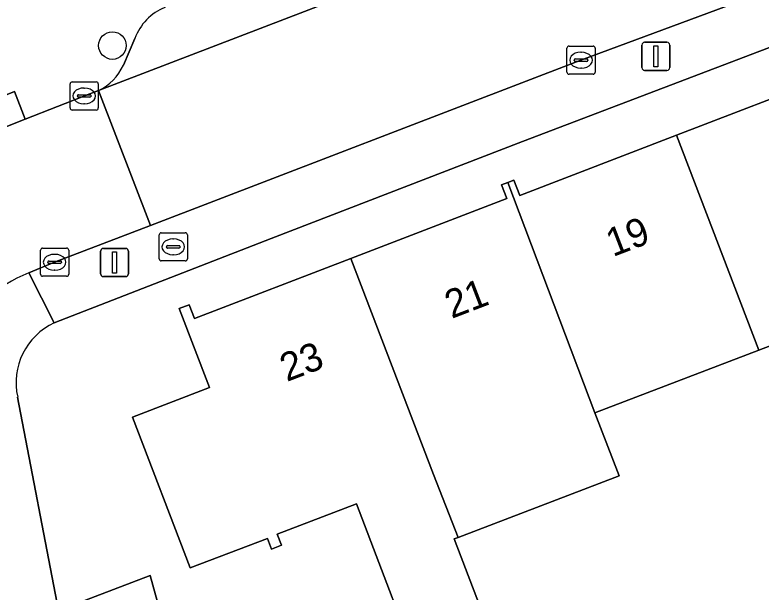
# Model space of a CAD drawing. Extents: x 159262 to 160143, y 383399 to 384319.
# Drawn here: x 159379.76 to 159406.24, y 383758.75 to 383779.23 of the extents above; entities that cross this region are included whole.
import ezdxf

# ---------------------------------------------------------------- set-up
doc = ezdxf.new("R2010")
doc.units = 0
for name, color, linetype in [('IMGEO_Boom', 7, 'Continuous'), ('IMGEO_Brandkraan', 7, 'Continuous'), ('IMGEO_Erf', 7, 'Continuous'), ('IMGEO_Kolk', 7, 'Continuous'), ('IMGEO_Lichtmast', 7, 'Continuous'), ('IMGEO_Pand', 7, 'Continuous'), ('IMGEO_Pand_nummerreeks', 7, 'Continuous'), ('IMGEO_Parkeervlak_open', 7, 'Continuous'), ('IMGEO_Rijbaan_lokaal_open', 7, 'Continuous'), ('IMGEO_Voetpad_open', 7, 'Continuous')]:
    doc.layers.add(name, color=color, linetype=linetype)

msp = doc.modelspace()

# ---------------------------------------------------------------- linework, layer by layer
at = {"layer": 'IMGEO_Boom'}
msp.add_circle((159383.218, 383778.141), 0.489, dxfattribs=at)
at = {"layer": 'IMGEO_Brandkraan'}
for p, q in [((159384.878, 383770.571), (159384.878, 383771.423)), ((159384.953, 383771.497), (159385.805, 383771.497)), ((159385.366, 383771.277), (159385.391, 383771.277)), ((159385.879, 383771.423), (159385.879, 383770.571)), ((159385.137, 383770.991), (159385.137, 383771.003)), ((159385.18, 383771.04), (159385.578, 383771.04)), ((159385.621, 383771.003), (159385.621, 383770.991)), ((159385.575, 383770.954), (159385.177, 383770.954)), ((159385.805, 383770.497), (159384.953, 383770.497)), ((159385.389, 383770.717), (159385.364, 383770.717))]:
    msp.add_line(p, q, dxfattribs=at)
for points in [[(159384.878, 383770.571), (159384.878, 383771.423)], [(159384.953, 383771.497), (159385.805, 383771.497)], [(159385.879, 383771.423), (159385.879, 383770.571)], [(159385.805, 383770.497), (159384.953, 383770.497)]]:
    msp.add_lwpolyline(points, dxfattribs=at)
for centre, radius, start, end in [((159384.955, 383771.421), 0.0765, 91.552, 178.448), ((159384.955, 383771.421), 0.0765, 91.552, 178.448), ((159385.803, 383771.421), 0.0765, 1.552, 88.448), ((159385.803, 383771.421), 0.0765, 1.552, 88.448), ((159385.177, 383771), 0.0403, 85.8775, 175.7526), ((159385.174, 383770.99), 0.0366, 178.938, 274.7102), ((159385.578, 383770.997), 0.043, 264.8664, 352.4533), ((159385.582, 383771.002), 0.0386, 1.7309, 96.639), ((159384.955, 383770.573), 0.0765, 181.552, 268.448), ((159384.955, 383770.573), 0.0765, 181.552, 268.448), ((159385.803, 383770.573), 0.0765, 271.552, 358.448), ((159385.803, 383770.573), 0.0765, 271.552, 358.448)]:
    msp.add_arc(centre, radius, start, end, dxfattribs=at)
for centre, major_axis, ratio, start_param, end_param in [((159385.365, 383770.997), (-0.387, 0.002), 0.722429, 4.712389, 7.853982), ((159385.39, 383770.997), (-0.39, 0.002), 0.717154, 1.570796, 4.712389)]:
    msp.add_ellipse(centre, major_axis=major_axis, ratio=ratio, start_param=start_param, end_param=end_param, dxfattribs=at)
at = {"layer": 'IMGEO_Erf'}
for points in [[(159454.891, 383796.495), (159397.777, 383774.733), (159388.854, 383771.293), (159381.158, 383768.297)], [(159383.927, 383764.958), (159386.663, 383766.007), (159385.588, 383768.807), (159385.945, 383768.945), (159386.133, 383768.456), (159391.678, 383770.585), (159397.219, 383772.712), (159397.031, 383773.199), (159397.25, 383773.283), (159397.468, 383773.367), (159397.676, 383772.825), (159403.232, 383774.958), (159408.79, 383777.092)], [(159411.906, 383769.536), (159406.156, 383767.336), (159400.339, 383765.112), (159401.208, 383762.87), (159395.493, 383760.684), (159395.351, 383760.63), (159397.605, 383754.719), (159397.792, 383754.791), (159401.541, 383756.23), (159402.437, 383753.896), (159417.698, 383760.02)], [(159379.857, 383765.664), (159381.308, 383758.091), (159384.559, 383759.339), (159385.65, 383755.4), (159382.115, 383753.813), (159382.7, 383750.83), (159394.45, 383755.134), (159391.879, 383761.875), (159389.07, 383760.801), (159389.22, 383760.409), (159388.866, 383760.273), (159388.72, 383760.653), (159385.981, 383759.602), (159383.927, 383764.958)]]:
    msp.add_lwpolyline(points, dxfattribs=at)
msp.add_arc((159382.118, 383766.185), 2.32, 114.4344, 192.9764, dxfattribs=at)
at = {"layer": 'IMGEO_Kolk'}
for p, q in [((159399.35, 383777.196), (159399.35, 383778.048)), ((159399.425, 383778.122), (159400.277, 383778.122)), ((159399.838, 383777.902), (159399.863, 383777.902)), ((159400.351, 383778.048), (159400.351, 383777.196)), ((159399.609, 383777.616), (159399.609, 383777.628)), ((159399.652, 383777.665), (159400.05, 383777.665)), ((159400.093, 383777.628), (159400.093, 383777.616)), ((159400.047, 383777.579), (159399.649, 383777.579)), ((159399.861, 383777.342), (159399.836, 383777.342)), ((159400.277, 383777.122), (159399.425, 383777.122)), ((159381.793, 383776.853), (159382.645, 383776.853)), ((159381.718, 383775.927), (159381.718, 383776.779)), ((159382.206, 383776.633), (159382.231, 383776.633)), ((159382.719, 383776.779), (159382.719, 383775.927)), ((159381.977, 383776.347), (159381.977, 383776.359)), ((159382.415, 383776.31), (159382.017, 383776.31)), ((159382.02, 383776.396), (159382.418, 383776.396)), ((159382.461, 383776.359), (159382.461, 383776.347)), ((159382.229, 383776.073), (159382.204, 383776.073)), ((159382.645, 383775.853), (159381.793, 383775.853)), ((159380.668, 383770.026), (159380.668, 383770.878)), ((159380.743, 383770.952), (159381.595, 383770.952)), ((159381.156, 383770.732), (159381.181, 383770.732)), ((159381.669, 383770.878), (159381.669, 383770.026)), ((159380.927, 383770.446), (159380.927, 383770.458)), ((159380.97, 383770.495), (159381.368, 383770.495)), ((159381.411, 383770.458), (159381.411, 383770.446)), ((159381.365, 383770.409), (159380.967, 383770.409)), ((159381.595, 383769.952), (159380.743, 383769.952)), ((159381.179, 383770.172), (159381.154, 383770.172))]:
    msp.add_line(p, q, dxfattribs=at)
for points in [[(159399.35, 383777.196), (159399.35, 383778.048)], [(159399.425, 383778.122), (159400.277, 383778.122)], [(159400.351, 383778.048), (159400.351, 383777.196)], [(159400.277, 383777.122), (159399.425, 383777.122)], [(159381.793, 383776.853), (159382.645, 383776.853)], [(159381.718, 383775.927), (159381.718, 383776.779)], [(159382.719, 383776.779), (159382.719, 383775.927)], [(159382.645, 383775.853), (159381.793, 383775.853)], [(159380.668, 383770.026), (159380.668, 383770.878)], [(159380.743, 383770.952), (159381.595, 383770.952)], [(159381.669, 383770.878), (159381.669, 383770.026)], [(159381.595, 383769.952), (159380.743, 383769.952)]]:
    msp.add_lwpolyline(points, dxfattribs=at)
for centre, radius, start, end in [((159399.427, 383778.046), 0.0765, 91.552, 178.448), ((159399.427, 383778.046), 0.0765, 91.552, 178.448), ((159400.275, 383778.046), 0.0765, 1.552, 88.448), ((159400.275, 383778.046), 0.0765, 1.552, 88.448), ((159399.649, 383777.625), 0.0403, 85.8775, 175.7526), ((159399.646, 383777.615), 0.0366, 178.938, 274.7102), ((159400.05, 383777.622), 0.043, 264.8664, 352.4533), ((159400.054, 383777.627), 0.0386, 1.7309, 96.639), ((159399.427, 383777.198), 0.0765, 181.552, 268.448), ((159399.427, 383777.198), 0.0765, 181.552, 268.448), ((159400.275, 383777.198), 0.0765, 271.552, 358.448), ((159400.275, 383777.198), 0.0765, 271.552, 358.448), ((159381.795, 383776.777), 0.0765, 91.552, 178.448), ((159381.795, 383776.777), 0.0765, 91.552, 178.448), ((159382.643, 383776.777), 0.0765, 1.552, 88.448), ((159382.643, 383776.777), 0.0765, 1.552, 88.448), ((159382.017, 383776.356), 0.0403, 85.8775, 175.7526), ((159382.014, 383776.346), 0.0366, 178.938, 274.7102), ((159382.418, 383776.353), 0.043, 264.8664, 352.4533), ((159382.422, 383776.358), 0.0386, 1.7309, 96.639), ((159381.795, 383775.929), 0.0765, 181.552, 268.448), ((159381.795, 383775.929), 0.0765, 181.552, 268.448), ((159382.643, 383775.929), 0.0765, 271.552, 358.448), ((159382.643, 383775.929), 0.0765, 271.552, 358.448), ((159380.745, 383770.876), 0.0765, 91.552, 178.448), ((159380.745, 383770.876), 0.0765, 91.552, 178.448), ((159381.593, 383770.876), 0.0765, 1.552, 88.448), ((159381.593, 383770.876), 0.0765, 1.552, 88.448), ((159380.967, 383770.455), 0.0403, 85.8775, 175.7526), ((159381.372, 383770.457), 0.0386, 1.7309, 96.639), ((159380.964, 383770.445), 0.0366, 178.938, 274.7102), ((159381.368, 383770.452), 0.043, 264.8664, 352.4533), ((159380.745, 383770.028), 0.0765, 181.552, 268.448), ((159380.745, 383770.028), 0.0765, 181.552, 268.448), ((159381.593, 383770.028), 0.0765, 271.552, 358.448), ((159381.593, 383770.028), 0.0765, 271.552, 358.448)]:
    msp.add_arc(centre, radius, start, end, dxfattribs=at)
for centre, major_axis, ratio, start_param, end_param in [((159399.837, 383777.622), (-0.387, 0.002), 0.722429, 4.712389, 7.853982), ((159399.862, 383777.622), (-0.39, 0.002), 0.717154, 1.570796, 4.712389), ((159382.205, 383776.353), (-0.387, 0.002), 0.722429, 4.712389, 7.853982), ((159382.23, 383776.353), (-0.39, 0.002), 0.717154, 1.570796, 4.712389), ((159381.155, 383770.452), (-0.387, 0.002), 0.722429, 4.712389, 7.853982), ((159381.18, 383770.452), (-0.39, 0.002), 0.717154, 1.570796, 4.712389)]:
    msp.add_ellipse(centre, major_axis=major_axis, ratio=ratio, start_param=start_param, end_param=end_param, dxfattribs=at)
at = {"layer": 'IMGEO_Lichtmast'}
for p, q in [((159402.007, 383777.359), (159402.007, 383778.159)), ((159402.007, 383778.159), (159402.007, 383777.359)), ((159402.107, 383778.259), (159402.897, 383778.259)), ((159402.897, 383778.259), (159402.107, 383778.259)), ((159402.997, 383778.159), (159402.997, 383777.359)), ((159402.997, 383777.359), (159402.997, 383778.159)), ((159402.897, 383777.259), (159402.107, 383777.259)), ((159402.107, 383777.259), (159402.897, 383777.259)), ((159382.8, 383770.043), (159382.8, 383770.843)), ((159382.8, 383770.843), (159382.8, 383770.043)), ((159382.9, 383770.943), (159383.69, 383770.943)), ((159383.69, 383770.943), (159382.9, 383770.943)), ((159383.79, 383770.843), (159383.79, 383770.043)), ((159383.79, 383770.043), (159383.79, 383770.843)), ((159383.69, 383769.943), (159382.9, 383769.943)), ((159382.9, 383769.943), (159383.69, 383769.943))]:
    msp.add_line(p, q, dxfattribs=at)
for points in [[(159402.427, 383778.134), (159402.577, 383778.134), (159402.577, 383777.384), (159402.427, 383777.384), (159402.427, 383778.134)], [(159383.22, 383770.818), (159383.37, 383770.818), (159383.37, 383770.068), (159383.22, 383770.068), (159383.22, 383770.818)]]:
    msp.add_lwpolyline(points, dxfattribs=at)
for centre, start, end in [((159402.107, 383778.159), 90, 180), ((159402.107, 383778.159), 90, 180), ((159402.897, 383778.159), 0, 90), ((159402.897, 383778.159), 360, 90), ((159402.107, 383777.359), 180, 270), ((159402.107, 383777.359), 180, 270), ((159402.897, 383777.359), 270, 0), ((159402.897, 383777.359), 270, 0), ((159382.9, 383770.843), 90, 180), ((159382.9, 383770.843), 90, 180), ((159383.69, 383770.843), 0, 90), ((159383.69, 383770.843), 360, 90), ((159382.9, 383770.043), 180, 270), ((159382.9, 383770.043), 180, 270), ((159383.69, 383770.043), 270, 0), ((159383.69, 383770.043), 270, 0)]:
    msp.add_arc(centre, 0.1, start, end, dxfattribs=at)
at = {"layer": 'IMGEO_Pand'}
for points in [[(159406.156, 383767.336), (159411.906, 383769.536), (159408.815, 383777.651), (159408.606, 383777.571), (159408.79, 383777.092), (159403.232, 383774.958)], [(159406.156, 383767.336), (159403.232, 383774.958), (159397.676, 383772.825), (159397.468, 383773.367), (159397.25, 383773.283), (159400.339, 383765.112)], [(159391.678, 383770.585), (159394.619, 383762.923), (159395.493, 383760.684), (159401.208, 383762.87), (159400.339, 383765.112), (159397.25, 383773.283), (159397.031, 383773.199), (159397.219, 383772.712)], [(159391.678, 383770.585), (159386.133, 383768.456), (159385.945, 383768.945), (159385.588, 383768.807), (159386.663, 383766.007), (159383.927, 383764.958), (159385.981, 383759.602), (159388.72, 383760.653), (159388.866, 383760.273), (159389.22, 383760.409), (159389.07, 383760.801), (159391.879, 383761.875), (159394.45, 383755.134), (159382.7, 383750.83), (159382.871, 383750), (159383.52, 383746.85), (159388.206, 383748.595), (159391.978, 383750), (159398.686, 383752.499), (159397.792, 383754.791), (159397.605, 383754.719), (159395.351, 383760.63), (159395.493, 383760.684), (159394.619, 383762.923)], [(159381.308, 383758.091), (159382.115, 383753.813), (159385.65, 383755.4), (159384.559, 383759.339)]]:
    msp.add_lwpolyline(points, close=True, dxfattribs=at)
at = {"layer": 'IMGEO_Parkeervlak_open'}
for points in [[(159382.731, 383776.545), (159398.361, 383782.558), (159413.843, 383788.378), (159430.813, 383794.888), (159451.704, 383802.889)], [(159384.015, 383778.392), (159383.608, 383777.443)]]:
    msp.add_lwpolyline(points, dxfattribs=at)
for centre, radius, start, end in [((159385.789, 383777.739), 1.89, 111.7958, 159.7854), ((159381.91, 383778.224), 1.869, 296.053, 335.3027)]:
    msp.add_arc(centre, radius, start, end, dxfattribs=at)
at = {"layer": 'IMGEO_Rijbaan_lokaal_open'}
msp.add_lwpolyline([(159420.987, 383785.667), (159432.691, 383790.083), (159442.971, 383794.05), (159451.565, 383797.259), (159454.155, 383798.309), (159456.91, 383799.271), (159455.084, 383804.175), (159451.704, 383802.889), (159430.813, 383794.888), (159413.843, 383788.378), (159398.361, 383782.558), (159382.731, 383776.545), (159384.569, 383771.758), (159399.847, 383777.623), (159409.934, 383781.376)], close=True, dxfattribs=at)
msp.add_lwpolyline([(159380.25, 383770.078), (159381.169, 383770.453), (159384.569, 383771.758), (159382.731, 383776.545), (159382.42, 383776.425), (159380.129, 383775.526), (159378.116, 383774.737), (159375.723, 383773.799)], dxfattribs=at)
msp.add_arc((159382.299, 383765.115), 5.369, 112.4347, 188.5158, dxfattribs=at)
at = {"layer": 'IMGEO_Voetpad_open'}
for points in [[(159458.547, 383794.996), (159457.253, 383798.289), (159454.498, 383797.327), (159454.155, 383798.309), (159451.565, 383797.259), (159442.971, 383794.05), (159432.691, 383790.083), (159420.987, 383785.667), (159409.934, 383781.376), (159399.847, 383777.623), (159384.569, 383771.758), (159381.169, 383770.453), (159380.25, 383770.078), (159381.158, 383768.297), (159388.854, 383771.293), (159397.777, 383774.733), (159454.891, 383796.495)], [(159383.608, 383777.443), (159384.015, 383778.392)], [(159375.341, 383774.766), (159377.913, 383775.783), (159379.742, 383776.506), (159380.129, 383775.526), (159382.42, 383776.425), (159382.731, 383776.545)], [(159378.116, 383774.737), (159380.129, 383775.526), (159379.742, 383776.506), (159377.913, 383775.783), (159375.341, 383774.766)], [(159381.158, 383768.297), (159380.25, 383770.078)], [(159383.732, 383745.39), (159383.52, 383746.85), (159382.871, 383750), (159382.7, 383750.83), (159382.115, 383753.813), (159381.308, 383758.091), (159379.857, 383765.664)]]:
    msp.add_lwpolyline(points, dxfattribs=at)
for centre, radius, start, end in [((159385.789, 383777.739), 1.89, 111.7958, 159.7854), ((159381.91, 383778.224), 1.869, 296.053, 335.3027), ((159382.299, 383765.115), 5.369, 112.4347, 188.5158), ((159382.118, 383766.185), 2.32, 114.4344, 192.9764)]:
    msp.add_arc(centre, radius, start, end, dxfattribs=at)

# ---------------------------------------------------------------- texts
at = {"layer": 'IMGEO_Pand_nummerreeks'}
for s, p in [('19', (159400.978, 383770.632)), ('21', (159395.256, 383768.438)), ('23', (159389.406, 383766.198))]:
    msp.add_text(s, height=1, rotation=20.9611, dxfattribs=at).set_placement(p)

doc.saveas('drawing.dxf')
